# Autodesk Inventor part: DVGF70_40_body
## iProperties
Created: 2010-04
Part Number: DVGF70_40_body
Document SubType Name: Modeling
Designer: TB
Mass: 1104.04 g
Surface Area: 1693.97 cm^2
Volume: 1104.04 cm^3
Density: 1 g/cm^3
Author: TB
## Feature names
1. Kropp [Revolution]
2. Chamfer
3. Extrusion2
4. Hole1
5. Revolution2
6. Hole2
7. Fillet1
8. Extrusion3
9. Hole3
